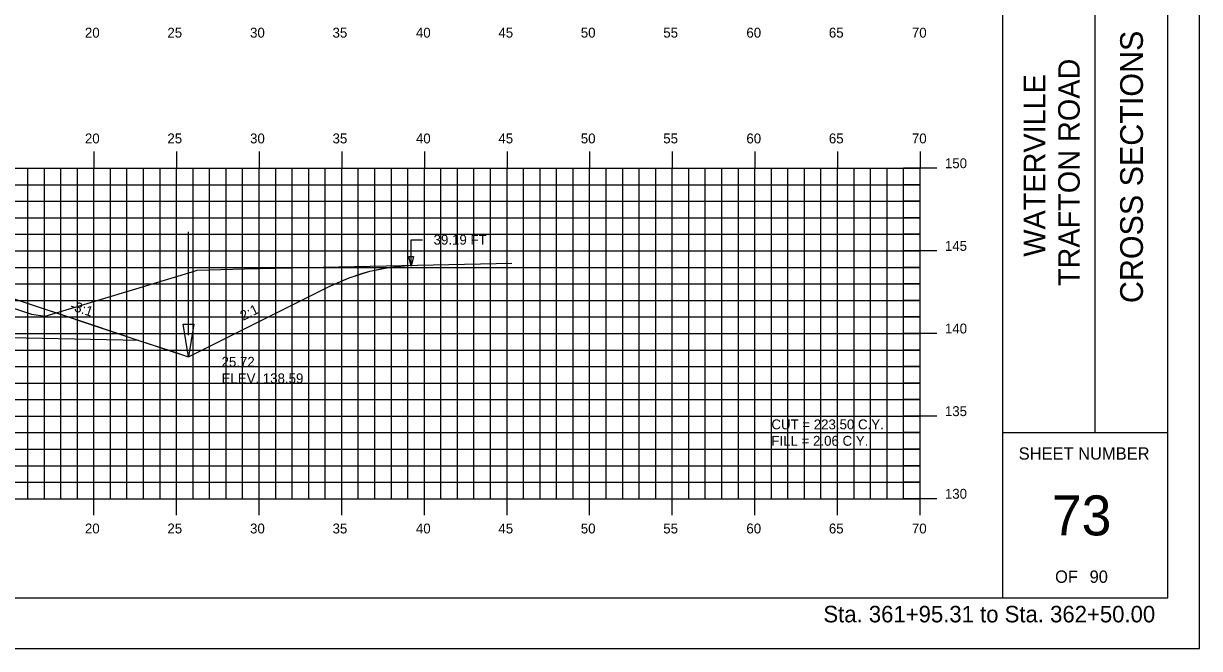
# Model space of a CAD drawing. Extents: x 1146746 to 1146916, y 608981 to 609091.
# Drawn here: x 1146845.2 to 1146916.3, y 608981.3 to 609019.1 of the extents above; entities that cross this region are included whole.
import ezdxf

# ---------------------------------------------------------------- set-up
doc = ezdxf.new("R2010")
doc.units = 0
for name, color, linetype in [('ANNOTATION', 7, 'Continuous'), ('BORDER', 7, 'Continuous'), ('D_Drainage_Ditch_Line', 7, 'Continuous'), ('D_Roadway_SlopeLines', 7, 'Continuous'), ('D_Roadway_SubGrade', 7, 'Continuous'), ('D_Text_Standard', 7, 'Continuous'), ('H_V ANNOTATION', 7, 'Continuous'), ('HIGHWAY_TITLE', 7, 'Continuous'), ('MAJOR', 7, 'Continuous'), ('MINOR', 7, 'Continuous'), ('PLOT BOUNDARY', 7, 'Continuous'), ('S_Roadway_Centerline', 7, 'Continuous')]:
    doc.layers.add(name, color=color, linetype=linetype)

msp = doc.modelspace()

# ---------------------------------------------------------------- linework, layer by layer
msp.add_lwpolyline([(1146844.428, 609002.495), (1146849.22, 609000.898), (1146852.151, 608999.92), (1146854.012, 608999.3), (1146855.151, 608998.92), (1146860.399, 609001.544), (1146863.621, 609003.155), (1146864.397, 609003.497), (1146864.871, 609003.706), (1146865.647, 609003.954), (1146866.121, 609004.106), (1146866.897, 609004.262), (1146867.371, 609004.357), (1146868.147, 609004.42), (1146868.621, 609004.459)])
at = {"layer": 'BORDER'}
for p, q in [((1146904.428, 608984.335), (1146904.428, 609089.335)), ((1146910.019, 608994.338), (1146910.019, 609029.338)), ((1146904.428, 608994.338), (1146914.428, 608994.338))]:
    msp.add_line(p, q, dxfattribs=at)
msp.add_lwpolyline([(1146754.428, 608984.335), (1146914.428, 608984.335), (1146914.428, 609089.335), (1146754.428, 609089.335)], close=True, dxfattribs=at)
at = {"layer": 'D_Drainage_Ditch_Line'}
msp.add_line((1146855.151, 609000.233), (1146855.152, 609006.476), dxfattribs=at)
msp.add_lwpolyline([(1146854.823, 609000.889), (1146855.479, 609000.889), (1146855.151, 608998.92)], close=True, dxfattribs=at)
at = {"layer": 'D_Roadway_SlopeLines'}
for points in [[(1146855.151, 608998.92), (1146863.621, 609003.155), (1146864.871, 609003.706), (1146866.121, 609004.106), (1146867.371, 609004.357), (1146868.621, 609004.459)], [(1146852.151, 608999.92), (1146855.151, 608998.92)]]:
    msp.add_lwpolyline(points, dxfattribs=at)
at = {"layer": 'D_Roadway_SubGrade'}
msp.add_lwpolyline([(1146840.428, 609002.238), (1146840.428, 609002.405), (1146844.428, 609002.245), (1146844.428, 609002.495), (1146844.428, 609002.495), (1146852.151, 608999.92), (1146840.428, 609000.155)], close=True, dxfattribs=at)
at = {"layer": 'D_Text_Standard'}
msp.add_lwpolyline([(1146868.621, 609004.405), (1146868.625, 609006.009), (1146869.305, 609006.009)], dxfattribs=at)
msp.add_lwpolyline([(1146868.621, 609004.405), (1146868.477, 609004.988), (1146868.768, 609004.987)], close=True, dxfattribs=at)
at = {"layer": 'MAJOR'}
for p, q in [((1146849.428, 609011.337), (1146849.428, 609010.335)), ((1146854.428, 609011.337), (1146854.428, 609010.335)), ((1146859.428, 609011.337), (1146859.428, 609010.335)), ((1146864.428, 609011.337), (1146864.428, 609010.335)), ((1146869.428, 609011.337), (1146869.428, 609010.335)), ((1146874.428, 609011.337), (1146874.428, 609010.335)), ((1146879.428, 609011.337), (1146879.428, 609010.335)), ((1146884.428, 609011.337), (1146884.428, 609010.335)), ((1146889.428, 609011.337), (1146889.428, 609010.335)), ((1146894.428, 609011.337), (1146894.428, 609010.335)), ((1146899.428, 609011.337), (1146899.428, 609010.335)), ((1146759.428, 609010.335), (1146899.428, 609010.335)), ((1146759.428, 609010.335), (1146899.428, 609010.335)), ((1146849.428, 608990.335), (1146849.428, 609010.335)), ((1146854.428, 608990.335), (1146854.428, 609010.335)), ((1146859.428, 608990.335), (1146859.428, 609010.335)), ((1146864.428, 608990.335), (1146864.428, 609010.335)), ((1146869.428, 608990.335), (1146869.428, 609010.335)), ((1146874.428, 608990.335), (1146874.428, 609010.335)), ((1146879.428, 608990.335), (1146879.428, 609010.335)), ((1146884.428, 608990.335), (1146884.428, 609010.335)), ((1146889.428, 608990.335), (1146889.428, 609010.335)), ((1146894.428, 608990.335), (1146894.428, 609010.335)), ((1146900.43, 609010.335), (1146898.426, 609010.335)), ((1146899.428, 608990.335), (1146899.428, 609010.335)), ((1146899.428, 608990.335), (1146899.428, 609010.335)), ((1146759.428, 609005.335), (1146899.428, 609005.335)), ((1146900.43, 609005.335), (1146898.426, 609005.335)), ((1146759.428, 609000.335), (1146899.428, 609000.335)), ((1146900.43, 609000.335), (1146898.426, 609000.335)), ((1146759.428, 608995.335), (1146899.428, 608995.335)), ((1146900.43, 608995.335), (1146898.426, 608995.335)), ((1146759.428, 608990.335), (1146899.428, 608990.335)), ((1146759.428, 608990.335), (1146899.428, 608990.335)), ((1146849.428, 608989.333), (1146849.428, 608990.335)), ((1146854.428, 608989.333), (1146854.428, 608990.335)), ((1146859.428, 608989.333), (1146859.428, 608990.335)), ((1146864.428, 608989.333), (1146864.428, 608990.335)), ((1146869.428, 608989.333), (1146869.428, 608990.335)), ((1146874.428, 608989.333), (1146874.428, 608990.335)), ((1146879.428, 608989.333), (1146879.428, 608990.335)), ((1146884.428, 608989.333), (1146884.428, 608990.335)), ((1146889.428, 608989.333), (1146889.428, 608990.335)), ((1146894.428, 608989.333), (1146894.428, 608990.335)), ((1146900.43, 608990.335), (1146898.426, 608990.335)), ((1146899.428, 608989.333), (1146899.428, 608990.335))]:
    msp.add_line(p, q, dxfattribs=at)
at = {"layer": 'MINOR'}
for p, q in [((1146845.428, 608990.335), (1146845.428, 609010.335)), ((1146846.428, 608990.335), (1146846.428, 609010.335)), ((1146847.428, 608990.335), (1146847.428, 609010.335)), ((1146848.428, 608990.335), (1146848.428, 609010.335)), ((1146850.428, 608990.335), (1146850.428, 609010.335)), ((1146851.428, 608990.335), (1146851.428, 609010.335)), ((1146852.428, 608990.335), (1146852.428, 609010.335)), ((1146853.428, 608990.335), (1146853.428, 609010.335)), ((1146855.428, 608990.335), (1146855.428, 609010.335)), ((1146856.428, 608990.335), (1146856.428, 609010.335)), ((1146857.428, 608990.335), (1146857.428, 609010.335)), ((1146858.428, 608990.335), (1146858.428, 609010.335)), ((1146860.428, 608990.335), (1146860.428, 609010.335)), ((1146861.428, 608990.335), (1146861.428, 609010.335)), ((1146862.428, 608990.335), (1146862.428, 609010.335)), ((1146863.428, 608990.335), (1146863.428, 609010.335)), ((1146865.428, 608990.335), (1146865.428, 609010.335)), ((1146866.428, 608990.335), (1146866.428, 609010.335)), ((1146867.428, 608990.335), (1146867.428, 609010.335)), ((1146868.428, 608990.335), (1146868.428, 609010.335)), ((1146870.428, 608990.335), (1146870.428, 609010.335)), ((1146871.428, 608990.335), (1146871.428, 609010.335)), ((1146872.428, 608990.335), (1146872.428, 609010.335)), ((1146873.428, 608990.335), (1146873.428, 609010.335)), ((1146875.428, 608990.335), (1146875.428, 609010.335)), ((1146876.428, 608990.335), (1146876.428, 609010.335)), ((1146877.428, 608990.335), (1146877.428, 609010.335)), ((1146878.428, 608990.335), (1146878.428, 609010.335)), ((1146880.428, 608990.335), (1146880.428, 609010.335)), ((1146881.428, 608990.335), (1146881.428, 609010.335)), ((1146882.428, 608990.335), (1146882.428, 609010.335)), ((1146883.428, 608990.335), (1146883.428, 609010.335)), ((1146885.428, 608990.335), (1146885.428, 609010.335)), ((1146886.428, 608990.335), (1146886.428, 609010.335)), ((1146887.428, 608990.335), (1146887.428, 609010.335)), ((1146888.428, 608990.335), (1146888.428, 609010.335)), ((1146890.428, 608990.335), (1146890.428, 609010.335)), ((1146891.428, 608990.335), (1146891.428, 609010.335)), ((1146892.428, 608990.335), (1146892.428, 609010.335)), ((1146893.428, 608990.335), (1146893.428, 609010.335)), ((1146895.428, 608990.335), (1146895.428, 609010.335)), ((1146896.428, 608990.335), (1146896.428, 609010.335)), ((1146897.428, 608990.335), (1146897.428, 609010.335)), ((1146898.428, 608990.335), (1146898.428, 609010.335)), ((1146759.428, 609009.335), (1146899.428, 609009.335)), ((1146899.428, 609009.335), (1146898.426, 609009.335)), ((1146759.428, 609008.335), (1146899.428, 609008.335)), ((1146899.428, 609008.335), (1146898.426, 609008.335)), ((1146759.428, 609007.335), (1146899.428, 609007.335)), ((1146899.428, 609007.335), (1146898.426, 609007.335)), ((1146759.428, 609006.335), (1146899.428, 609006.335)), ((1146899.428, 609006.335), (1146898.426, 609006.335)), ((1146759.428, 609004.335), (1146899.428, 609004.335)), ((1146899.428, 609004.335), (1146898.426, 609004.335)), ((1146759.428, 609003.335), (1146899.428, 609003.335)), ((1146899.428, 609003.335), (1146898.426, 609003.335)), ((1146759.428, 609002.335), (1146899.428, 609002.335)), ((1146899.428, 609002.335), (1146898.426, 609002.335)), ((1146759.428, 609001.335), (1146899.428, 609001.335)), ((1146899.428, 609001.335), (1146898.426, 609001.335)), ((1146759.428, 608999.335), (1146899.428, 608999.335)), ((1146899.428, 608999.335), (1146898.426, 608999.335)), ((1146759.428, 608998.335), (1146899.428, 608998.335)), ((1146899.428, 608998.335), (1146898.426, 608998.335)), ((1146759.428, 608997.335), (1146899.428, 608997.335)), ((1146899.428, 608997.335), (1146898.426, 608997.335)), ((1146759.428, 608996.335), (1146899.428, 608996.335)), ((1146899.428, 608996.335), (1146898.426, 608996.335)), ((1146759.428, 608994.335), (1146899.428, 608994.335)), ((1146899.428, 608994.335), (1146898.426, 608994.335)), ((1146759.428, 608993.335), (1146899.428, 608993.335)), ((1146899.428, 608993.335), (1146898.426, 608993.335)), ((1146759.428, 608992.335), (1146899.428, 608992.335)), ((1146899.428, 608992.335), (1146898.426, 608992.335)), ((1146759.428, 608991.335), (1146899.428, 608991.335)), ((1146899.428, 608991.335), (1146898.426, 608991.335))]:
    msp.add_line(p, q, dxfattribs=at)
at = {"layer": 'PLOT BOUNDARY'}
msp.add_lwpolyline([(1146746.335, 608981.276), (1146916.335, 608981.276), (1146916.335, 609091.276), (1146746.335, 609091.276)], close=True, dxfattribs=at)
at = {"layer": 'S_Roadway_Centerline'}
msp.add_lwpolyline([(1146843.55, 609002.193), (1146845.656, 609001.505), (1146846.475, 609001.383), (1146855.38, 609004.074), (1146855.685, 609004.168), (1146858.549, 609004.244), (1146874.72, 609004.589)], dxfattribs=at)

# ---------------------------------------------------------------- texts
at = {"layer": 'ANNOTATION'}
for s, rotation, p in [('-3:1', 341.56528, (1146847.939, 609001.779)), ('2:1', 26.56505, (1146858.459, 609001.092))]:
    msp.add_text(s, height=0.6, rotation=rotation, dxfattribs=at).set_placement(p)
at = {"layer": 'BORDER'}
msp.add_text('CROSS SECTIONS', height=1.37787, rotation=90, dxfattribs=at).set_placement((1146912.912, 609002.172))
for s, height, p in [('SHEET NUMBER', 0.74527, (1146905.393, 608992.701)), ('73', 2.4194, (1146907.404, 608988.118)), ('OF', 0.7453, (1146907.595, 608985.248)), ('90', 0.7453, (1146909.684, 608985.248))]:
    msp.add_text(s, height=height, dxfattribs=at).set_placement(p)
at = {"layer": 'D_Text_Standard'}
for s, p in [('39.19 FT', (1146869.985, 609005.709)), ('25.72', (1146857.151, 608998.32)), ('ELEV. 138.59', (1146857.151, 608997.318)), ('CUT = 223.50 C.Y.', (1146890.428, 608994.535)), ('FILL = 2.06 C.Y.', (1146890.428, 608993.539))]:
    msp.add_text(s, height=0.6, dxfattribs=at).set_placement(p)
at = {"layer": 'H_V ANNOTATION'}
for s, height, p in [('20', 0.6, (1146848.882, 609018.235)), ('25', 0.6, (1146853.874, 609018.235)), ('30', 0.6, (1146858.876, 609018.235)), ('35', 0.6, (1146863.868, 609018.235)), ('40', 0.6, (1146868.914, 609018.235)), ('45', 0.6, (1146873.906, 609018.235)), ('50', 0.6, (1146878.892, 609018.235)), ('55', 0.6, (1146883.884, 609018.235)), ('60', 0.6, (1146888.914, 609018.235)), ('65', 0.6, (1146893.906, 609018.235)), ('70', 0.6, (1146898.93, 609018.235)), ('20', 0.6, (1146848.882, 609011.835)), ('25', 0.6, (1146853.874, 609011.835)), ('30', 0.6, (1146858.876, 609011.835)), ('35', 0.6, (1146863.868, 609011.835)), ('40', 0.6, (1146868.914, 609011.835)), ('45', 0.6, (1146873.906, 609011.835)), ('50', 0.6, (1146878.892, 609011.835)), ('55', 0.6, (1146883.884, 609011.835)), ('60', 0.6, (1146888.914, 609011.835)), ('65', 0.6, (1146893.906, 609011.835)), ('70', 0.6, (1146898.93, 609011.835)), ('150', 0.6, (1146900.928, 609010.335)), ('145', 0.6, (1146900.928, 609005.335)), ('140', 0.6, (1146900.928, 609000.335)), ('135', 0.6, (1146900.928, 608995.335)), ('130', 0.6, (1146900.928, 608990.335)), ('20', 0.6, (1146848.882, 608988.235)), ('25', 0.6, (1146853.874, 608988.235)), ('30', 0.6, (1146858.876, 608988.235)), ('35', 0.6, (1146863.868, 608988.235)), ('40', 0.6, (1146868.914, 608988.235)), ('45', 0.6, (1146873.906, 608988.235)), ('50', 0.6, (1146878.892, 608988.235)), ('55', 0.6, (1146883.884, 608988.235)), ('60', 0.6, (1146888.914, 608988.235)), ('65', 0.6, (1146893.906, 608988.235)), ('70', 0.6, (1146898.93, 608988.235)), ('Sta. 361+95.31 to Sta. 362+50.00', 1.0002, (1146893.574, 608982.855))]:
    msp.add_text(s, height=height, dxfattribs=at).set_placement(p)
at = {"layer": 'HIGHWAY_TITLE'}
for s, height, p in [('TRAFTON ROAD', 1.30428, (1146909.087, 609003.201)), ('WATERVILLE', 1.3043, (1146907, 609004.98))]:
    msp.add_text(s, height=height, rotation=90, dxfattribs=at).set_placement(p)

doc.saveas('drawing.dxf')
